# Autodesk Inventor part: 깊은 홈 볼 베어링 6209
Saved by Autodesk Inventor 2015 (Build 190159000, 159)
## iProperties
Created: 2025-06
Part Number: 깊은 홈 볼 베어링 6209
Material: 일반
Document SubType Name: Modeling
Designer: User
Density: 1 g/cm^3
Appearance: 기본값
Author: User
Author: jhkim
Description: 깊은 그루부 볼 베어링
Creation Date: 2025-05-23
Sending System: Autodesk Inventor 2026
Preprocessor: ST-DEVELOPER v20.1
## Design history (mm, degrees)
node "깊은 홈 볼 베어링 62091"
body "Solid1"
node "Solid1_1"
node "Solid1_2"
node "Solid1_3"
node "Solid1_4"
node "Solid1_5"
node "Solid1_6"
node "Solid1_7"
node "Solid1_8"
node "Solid1_9"
node "Solid1_10"
node "Solid1_11"
node "기준1"
node "기준2"
node "기준3"
node "기준4"
node "기준5"
node "기준6"
node "기준7"
node "기준8"
node "기준9"
node "기준10"
node "기준11"
node "기준12"
